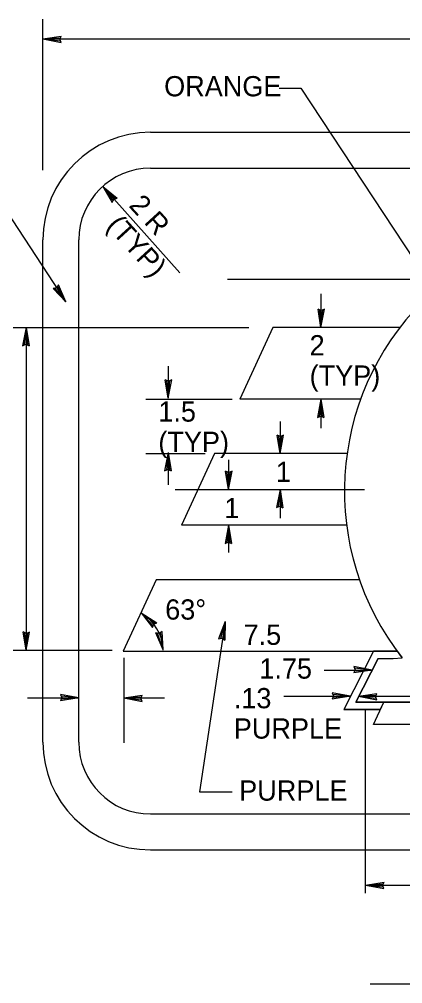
# Model space of a CAD drawing. Extents: x 10268197 to 10269179, y 2141503 to 2142677.
# Drawn here: x 10268524.24 to 10268537.59, y 2141960.82 to 2141994.42 of the extents above; entities that cross this region are included whole.
import ezdxf

# ---------------------------------------------------------------- set-up
doc = ezdxf.new("R2010")
doc.units = 0
for name, color, linetype in [('1', 7, 'Continuous'), ('21', 7, 'Continuous'), ('Default', 7, 'Continuous'), ('TextMisc', 7, 'Continuous'), ('TextShtNo', 7, 'Continuous')]:
    doc.layers.add(name, color=color, linetype=linetype)

msp = doc.modelspace()

# ---------------------------------------------------------------- linework, layer by layer
at = {"layer": '1'}
for p, q in [((10268527.147, 2141988.595), (10268529.832, 2141985.588)), ((10268531.404, 2141973.436), (10268530.515, 2141967.497)), ((10268536.809, 2141970.376), (10268535.542, 2141970.376)), ((10268530.515, 2141967.497), (10268531.648, 2141967.497))]:
    msp.add_line(p, q, dxfattribs=at)
msp.add_ellipse((10268527.755, 2141972.42), major_axis=(0, 1.49), ratio=0.999997, start_param=4.726798, end_param=5.778675, dxfattribs=at)
at = {"layer": '21'}
msp.add_line((10268536.456, 2141960.817), (10268546.168, 2141960.817), dxfattribs=at)
at = {"layer": 'Default'}
for p, q in [((10268525.062, 2141993.734), (10268525.701, 2141993.835)), ((10268525.062, 2141993.734), (10268525.674, 2141993.777)), ((10268525.062, 2141993.734), (10268557.562, 2141993.734)), ((10268525.062, 2141993.734), (10268525.697, 2141993.61)), ((10268525.062, 2141993.734), (10268525.673, 2141993.67)), ((10268525.65, 2141993.724), (10268525.701, 2141993.835)), ((10268525.697, 2141993.61), (10268525.65, 2141993.724)), ((10268533.286, 2141992.02), (10268534.043, 2141992.02)), ((10268534.043, 2141992.02), (10268539.153, 2141984.256)), ((10268528.812, 2141989.23), (10268553.812, 2141989.23)), ((10268527.147, 2141988.595), (10268527.649, 2141988.186)), ((10268527.147, 2141988.595), (10268527.478, 2141988.039)), ((10268527.147, 2141988.595), (10268527.506, 2141988.096)), ((10268527.147, 2141988.595), (10268527.587, 2141988.167)), ((10268523.56, 2141988.07), (10268525.862, 2141984.571)), ((10268527.478, 2141988.039), (10268527.531, 2141988.149)), ((10268527.531, 2141988.149), (10268527.649, 2141988.186)), ((10268526.312, 2141969.23), (10268526.312, 2141986.73)), ((10268531.49, 2141985.364), (10268542.826, 2141985.364)), ((10268525.539, 2141985.063), (10268525.418, 2141985.042)), ((10268525.862, 2141984.571), (10268525.418, 2141985.042)), ((10268525.862, 2141984.571), (10268525.482, 2141985.053)), ((10268525.606, 2141985.165), (10268525.539, 2141985.063)), ((10268525.862, 2141984.571), (10268525.57, 2141985.112)), ((10268525.862, 2141984.571), (10268525.606, 2141985.165)), ((10268534.745, 2141984.851), (10268534.745, 2141983.683)), ((10268534.745, 2141983.683), (10268534.644, 2141984.322)), ((10268534.755, 2141984.271), (10268534.644, 2141984.322)), ((10268534.745, 2141983.683), (10268534.702, 2141984.295)), ((10268534.745, 2141983.683), (10268534.869, 2141984.318)), ((10268534.745, 2141983.683), (10268534.809, 2141984.294)), ((10268534.869, 2141984.318), (10268534.755, 2141984.271)), ((10268524.026, 2141983.683), (10268532.233, 2141983.683)), ((10268524.479, 2141983.683), (10268524.356, 2141983.047)), ((10268524.479, 2141983.683), (10268524.415, 2141983.071)), ((10268524.479, 2141983.683), (10268524.479, 2141972.433)), ((10268524.479, 2141983.683), (10268524.58, 2141983.043)), ((10268524.479, 2141983.683), (10268524.522, 2141983.07)), ((10268533.07, 2141983.683), (10268531.915, 2141981.183)), ((10268537.495, 2141983.683), (10268533.07, 2141983.683)), ((10268524.356, 2141983.047), (10268524.469, 2141983.094)), ((10268524.469, 2141983.094), (10268524.58, 2141983.043)), ((10268529.425, 2141982.328), (10268529.425, 2141981.219)), ((10268529.425, 2141981.219), (10268529.324, 2141981.858)), ((10268529.435, 2141981.808), (10268529.324, 2141981.858)), ((10268529.425, 2141981.219), (10268529.382, 2141981.831)), ((10268529.425, 2141981.219), (10268529.548, 2141981.855)), ((10268529.425, 2141981.219), (10268529.488, 2141981.83)), ((10268529.548, 2141981.855), (10268529.435, 2141981.808)), ((10268528.645, 2141981.183), (10268531.651, 2141981.183)), ((10268536.125, 2141981.183), (10268531.915, 2141981.183)), ((10268534.745, 2141981.183), (10268534.622, 2141980.547)), ((10268534.745, 2141981.183), (10268534.681, 2141980.571)), ((10268534.745, 2141981.183), (10268534.745, 2141980.177)), ((10268534.745, 2141981.183), (10268534.847, 2141980.543)), ((10268534.745, 2141981.183), (10268534.789, 2141980.57)), ((10268534.622, 2141980.547), (10268534.735, 2141980.594)), ((10268534.735, 2141980.594), (10268534.847, 2141980.543)), ((10268533.321, 2141980.405), (10268533.321, 2141979.289)), ((10268533.321, 2141979.289), (10268533.22, 2141979.928)), ((10268533.331, 2141979.878), (10268533.22, 2141979.928)), ((10268533.321, 2141979.289), (10268533.278, 2141979.901)), ((10268533.321, 2141979.289), (10268533.444, 2141979.925)), ((10268533.321, 2141979.289), (10268533.385, 2141979.9)), ((10268533.444, 2141979.925), (10268533.331, 2141979.878)), ((10268528.645, 2141979.289), (10268530.712, 2141979.289)), ((10268529.425, 2141979.324), (10268529.302, 2141978.688)), ((10268529.425, 2141979.324), (10268529.361, 2141978.713)), ((10268529.425, 2141979.324), (10268529.425, 2141978.194)), ((10268529.425, 2141979.324), (10268529.526, 2141978.684)), ((10268529.425, 2141979.324), (10268529.468, 2141978.711)), ((10268531.041, 2141979.289), (10268529.886, 2141976.789)), ((10268535.654, 2141979.289), (10268531.041, 2141979.289)), ((10268531.526, 2141979.066), (10268531.526, 2141978.039)), ((10268529.302, 2141978.688), (10268529.415, 2141978.735)), ((10268529.415, 2141978.735), (10268529.526, 2141978.684)), ((10268531.526, 2141978.039), (10268531.425, 2141978.678)), ((10268531.536, 2141978.628), (10268531.425, 2141978.678)), ((10268531.526, 2141978.039), (10268531.483, 2141978.651)), ((10268531.526, 2141978.039), (10268531.649, 2141978.675)), ((10268531.526, 2141978.039), (10268531.59, 2141978.65)), ((10268531.649, 2141978.675), (10268531.536, 2141978.628)), ((10268529.666, 2141978.039), (10268536.264, 2141978.039)), ((10268533.321, 2141978.039), (10268533.198, 2141977.403)), ((10268533.321, 2141978.039), (10268533.258, 2141977.427)), ((10268533.321, 2141978.039), (10268533.321, 2141977.042)), ((10268533.321, 2141978.039), (10268533.422, 2141977.4)), ((10268533.321, 2141978.039), (10268533.364, 2141977.426)), ((10268533.198, 2141977.403), (10268533.311, 2141977.45)), ((10268533.311, 2141977.45), (10268533.422, 2141977.4)), ((10268535.638, 2141976.789), (10268529.886, 2141976.789)), ((10268531.526, 2141976.789), (10268531.403, 2141976.153)), ((10268531.526, 2141976.789), (10268531.462, 2141976.177)), ((10268531.526, 2141976.789), (10268531.526, 2141975.845)), ((10268531.526, 2141976.789), (10268531.627, 2141976.149)), ((10268531.526, 2141976.789), (10268531.569, 2141976.176)), ((10268531.403, 2141976.153), (10268531.516, 2141976.2)), ((10268531.516, 2141976.2), (10268531.627, 2141976.149)), ((10268529.011, 2141974.894), (10268527.861, 2141972.405)), ((10268536.06, 2141974.894), (10268529.011, 2141974.894)), ((10268528.484, 2141973.734), (10268529.033, 2141973.392)), ((10268528.484, 2141973.734), (10268528.883, 2141973.225)), ((10268528.484, 2141973.734), (10268528.903, 2141973.286)), ((10268528.484, 2141973.734), (10268528.974, 2141973.366)), ((10268528.883, 2141973.225), (10268528.921, 2141973.341)), ((10268528.921, 2141973.341), (10268529.033, 2141973.392)), ((10268531.404, 2141973.436), (10268531.178, 2141972.829)), ((10268531.404, 2141973.436), (10268531.241, 2141972.844)), ((10268531.404, 2141973.436), (10268531.346, 2141972.825)), ((10268531.404, 2141973.436), (10268531.4, 2141972.788)), ((10268524.479, 2141972.433), (10268524.378, 2141973.072)), ((10268524.489, 2141973.021), (10268524.378, 2141973.072)), ((10268524.479, 2141972.433), (10268524.436, 2141973.045)), ((10268524.479, 2141972.433), (10268524.602, 2141973.068)), ((10268524.479, 2141972.433), (10268524.543, 2141973.044)), ((10268524.602, 2141973.068), (10268524.489, 2141973.021)), ((10268529.255, 2141972.445), (10268528.993, 2141973.038)), ((10268529.115, 2141973.018), (10268528.993, 2141973.038)), ((10268529.255, 2141972.445), (10268529.057, 2141973.027)), ((10268529.212, 2141973.092), (10268529.115, 2141973.018)), ((10268529.255, 2141972.445), (10268529.16, 2141973.052)), ((10268529.255, 2141972.445), (10268529.212, 2141973.092)), ((10268531.178, 2141972.829), (10268531.297, 2141972.857)), ((10268531.297, 2141972.857), (10268531.4, 2141972.788)), ((10268524.026, 2141972.433), (10268527.475, 2141972.433)), ((10268527.861, 2141972.405), (10268537.379, 2141972.405)), ((10268527.88, 2141972.169), (10268527.88, 2141969.204)), ((10268536.574, 2141972.405), (10268535.542, 2141970.376)), ((10268536.73, 2141972.151), (10268535.956, 2141970.63)), ((10268536.574, 2141972.405), (10268537.403, 2141972.405)), ((10268536.73, 2141972.151), (10268537.263, 2141972.151)), ((10268537.263, 2141972.151), (10268537.574, 2141972.175)), ((10268536.524, 2141971.746), (10268535.888, 2141971.87)), ((10268535.888, 2141971.87), (10268535.935, 2141971.756)), ((10268536.524, 2141971.746), (10268535.913, 2141971.81)), ((10268534.856, 2141971.746), (10268536.524, 2141971.746)), ((10268535.935, 2141971.756), (10268535.885, 2141971.645)), ((10268536.524, 2141971.746), (10268535.885, 2141971.645)), ((10268536.524, 2141971.746), (10268535.912, 2141971.703)), ((10268524.522, 2141970.774), (10268526.312, 2141970.774)), ((10268525.723, 2141970.784), (10268525.672, 2141970.673)), ((10268526.312, 2141970.774), (10268525.672, 2141970.673)), ((10268526.312, 2141970.774), (10268525.676, 2141970.897)), ((10268525.676, 2141970.897), (10268525.723, 2141970.784)), ((10268526.312, 2141970.774), (10268525.699, 2141970.731)), ((10268526.312, 2141970.774), (10268525.7, 2141970.838)), ((10268527.88, 2141970.774), (10268528.519, 2141970.875)), ((10268527.88, 2141970.774), (10268528.492, 2141970.817)), ((10268527.88, 2141970.774), (10268529.296, 2141970.774)), ((10268527.88, 2141970.774), (10268528.516, 2141970.651)), ((10268527.88, 2141970.774), (10268528.491, 2141970.711)), ((10268528.469, 2141970.765), (10268528.519, 2141970.875)), ((10268533.45, 2141970.832), (10268535.769, 2141970.832)), ((10268535.18, 2141970.842), (10268535.13, 2141970.731)), ((10268535.769, 2141970.832), (10268535.13, 2141970.731)), ((10268535.769, 2141970.832), (10268535.133, 2141970.955)), ((10268535.133, 2141970.955), (10268535.18, 2141970.842)), ((10268535.769, 2141970.832), (10268535.157, 2141970.789)), ((10268535.769, 2141970.832), (10268535.158, 2141970.896)), ((10268536.053, 2141970.832), (10268536.693, 2141970.933)), ((10268536.053, 2141970.832), (10268536.666, 2141970.875)), ((10268536.053, 2141970.832), (10268537.961, 2141970.832)), ((10268536.053, 2141970.832), (10268536.689, 2141970.709)), ((10268536.053, 2141970.832), (10268536.665, 2141970.768)), ((10268536.642, 2141970.822), (10268536.693, 2141970.933)), ((10268536.689, 2141970.709), (10268536.642, 2141970.822)), ((10268528.516, 2141970.651), (10268528.469, 2141970.765)), ((10268535.956, 2141970.63), (10268537.05, 2141970.63)), ((10268536.569, 2141969.854), (10268536.927, 2141970.63)), ((10268548.175, 2141970.63), (10268536.927, 2141970.63)), ((10268536.3, 2141963.966), (10268536.3, 2141970.388)), ((10268548.869, 2141969.854), (10268536.569, 2141969.854)), ((10268528.812, 2141966.73), (10268553.812, 2141966.73)), ((10268536.3, 2141964.256), (10268536.94, 2141964.357)), ((10268536.3, 2141964.256), (10268536.913, 2141964.299)), ((10268536.3, 2141964.256), (10268548.175, 2141964.256)), ((10268536.3, 2141964.256), (10268536.936, 2141964.133)), ((10268536.3, 2141964.256), (10268536.912, 2141964.192)), ((10268536.889, 2141964.246), (10268536.94, 2141964.357)), ((10268536.936, 2141964.133), (10268536.889, 2141964.246))]:
    msp.add_line(p, q, dxfattribs=at)
for centre, major_axis, start_param, end_param in [((10268528.811, 2141986.73), (0, 2.5), 0, 1.570796), ((10268544.936, 2141977.98), (0, 9.375), 5.619293, 8.52162), ((10268528.811, 2141969.23), (0, -2.5), 4.712389, 6.283185)]:
    msp.add_ellipse(centre, major_axis=major_axis, ratio=0.999997, start_param=start_param, end_param=end_param, dxfattribs=at)
at = {"layer": 'TextMisc'}
for p, q in [((10268525.062, 2141989.16), (10268525.062, 2141994.418)), ((10268528.812, 2141990.48), (10268553.812, 2141990.48)), ((10268525.062, 2141969.23), (10268525.062, 2141986.73)), ((10268528.812, 2141965.48), (10268553.812, 2141965.48))]:
    msp.add_line(p, q, dxfattribs=at)
for centre, major_axis, start_param, end_param in [((10268528.811, 2141986.73), (0, 3.75), 0, 1.570796), ((10268528.811, 2141969.23), (0, -3.75), 4.712389, 6.283185)]:
    msp.add_ellipse(centre, major_axis=major_axis, ratio=0.999998, start_param=start_param, end_param=end_param, dxfattribs=at)
at = {"layer": 'TextShtNo'}
for p, q in [((10268536.569, 2141969.854), (10268536.927, 2141970.63)), ((10268536.927, 2141970.63), (10268548.175, 2141970.63)), ((10268548.869, 2141969.854), (10268536.569, 2141969.854))]:
    msp.add_line(p, q, dxfattribs=at)
msp.add_lwpolyline([(10268537.403, 2141972.405), (10268536.574, 2141972.405), (10268535.542, 2141970.376), (10268536.809, 2141970.376), (10268536.927, 2141970.63), (10268535.956, 2141970.63), (10268536.73, 2141972.151), (10268537.263, 2141972.151), (10268537.574, 2141972.175)], close=True, dxfattribs=at)

# ---------------------------------------------------------------- texts
at = {"layer": '1'}
for s, height, p in [('ORANGE', 0.7047, (10268529.284, 2141991.734)), ('2', 0.705, (10268534.348, 2141982.709)), ('(TYP)', 0.7047, (10268534.348, 2141981.652)), ('1.5', 0.7047, (10268529.082, 2141980.4)), ('(TYP)', 0.7047, (10268529.082, 2141979.343)), ('1', 0.705, (10268533.174, 2141978.299)), ('1', 0.705, (10268531.38, 2141977.039)), ('63°', 0.7047, (10268529.321, 2141973.503)), ('7.5', 0.7047, (10268532.049, 2141972.623)), ('1.75', 0.7047, (10268532.598, 2141971.446)), ('.13', 0.7047, (10268531.709, 2141970.414)), ('PURPLE', 0.7047, (10268531.709, 2141969.357)), ('PURPLE', 0.7047, (10268531.896, 2141967.195))]:
    msp.add_text(s, height=height, dxfattribs=at).set_placement(p)
for s, p in [('2 R', (10268528.027, 2141987.911)), ('(TYP)', (10268527.247, 2141987.198))]:
    msp.add_text(s, height=0.7047, rotation=312.435, dxfattribs=at).set_placement(p)

doc.saveas('drawing.dxf')
